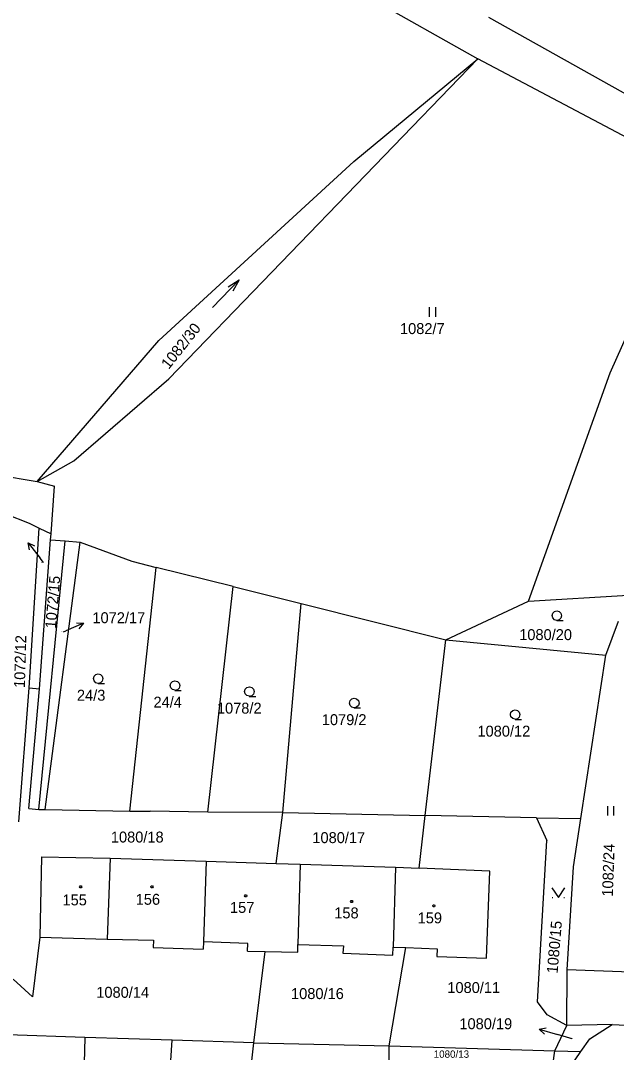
# Model space of a CAD drawing. Extents: x -850689 to -847910, y -1058374 to -1054747.
# Drawn here: x -849516.8 to -849424.1, y -1056255.5 to -1056094.9 of the extents above; entities that cross this region are included whole.
import ezdxf

# ---------------------------------------------------------------- set-up
doc = ezdxf.new("R2010")
doc.units = 0
for name, color, linetype in [('KN_HRANICE', 7, 'Continuous'), ('KN_KULTURY', 7, 'Continuous'), ('KN_PARCELY', 7, 'Continuous'), ('KN_STAVEBNI', 7, 'Continuous')]:
    doc.layers.add(name, color=color, linetype=linetype)

# ---------------------------------------------------------------- blocks, each defined once
blk = doc.blocks.new('304')
blk.add_lwpolyline([(0, 0), (-0.38, 0.1), (-0.65, 0.37), (-0.75, 0.74), (-0.65, 1.11), (-0.38, 1.38), (-0.01, 1.48), (0.36, 1.38), (0.63, 1.11), (0.73, 0.73), (0.63, 0.35), (0.36, 0.08), (-0.02, -0.02), (0.98, -0.02)])
blk = doc.blocks.new('306')
for p, q in [((-0.5, 1.5), (-0.5, 0)), ((0.5, 0), (0.5, 1.5))]:
    blk.add_line(p, q)
blk = doc.blocks.new('314')
for p, q in [((-0.95, 0), (-0.85, 0)), ((0.85, 0), (0.95, 0))]:
    blk.add_line(p, q)
blk.add_lwpolyline([(-1, 1.5), (0, 0), (1, 1.5)])
blk = doc.blocks.new('802')
blk.add_line((-3, 0), (3, 0))
blk.add_lwpolyline([(1, 0.5), (3, 0), (1, -0.5)])
blk = doc.blocks.new('10292')
blk.add_line((0, 3), (0, 0))
blk.add_lwpolyline([(-0.5, 2), (0, 3), (0.5, 2)])
blk = doc.blocks.new('402')
blk.add_lwpolyline([(0.09, 0.15), (0.18, 0), (0.09, -0.15), (-0.09, -0.15), (-0.18, 0), (-0.09, 0.15), (0.09, 0.15)])

msp = doc.modelspace()

# ---------------------------------------------------------------- linework, layer by layer
at = {"layer": 'KN_HRANICE'}
for p, q in [((-849544.37, -1056045.31), (-849445.63, -1056100.85)), ((-849443.99, -1056094.41), (-849418.2, -1056108.82)), ((-849493.74, -1056150.69), (-849445.63, -1056100.85)), ((-849464.96, -1056116.83), (-849445.63, -1056100.85)), ((-849411.33, -1056119.03), (-849445.63, -1056100.85)), ((-849495.31, -1056144.7), (-849464.96, -1056116.83)), ((-849425.04, -1056149.71), (-849411.33, -1056119.03)), ((-849514.22, -1056166.62), (-849495.31, -1056144.7)), ((-849508.53, -1056163.41), (-849493.74, -1056150.69)), ((-849437.73, -1056185.24), (-849425.04, -1056149.71)), ((-849514.22, -1056166.62), (-849508.53, -1056163.41)), ((-849524.53, -1056164.91), (-849514.22, -1056166.62)), ((-849514.22, -1056166.62), (-849511.52, -1056167.35)), ((-849512.08, -1056174.78), (-849511.52, -1056167.35)), ((-849519.17, -1056171.69), (-849515.51, -1056173.13)), ((-849515.51, -1056173.13), (-849513.93, -1056173.89)), ((-849515.49, -1056198.73), (-849513.93, -1056173.89)), ((-849513.93, -1056173.89), (-849512.08, -1056174.78)), ((-849512.15, -1056175.71), (-849512.08, -1056174.78)), ((-849513.99, -1056217.66), (-849509.86, -1056175.89)), ((-849513.9, -1056198.93), (-849512.15, -1056175.71)), ((-849512.99, -1056217.67), (-849507.57, -1056176.06)), ((-849512.15, -1056175.71), (-849509.86, -1056175.89)), ((-849509.86, -1056175.89), (-849507.57, -1056176.06)), ((-849507.57, -1056176.06), (-849499.52, -1056179.04)), ((-849499.52, -1056179.04), (-849495.72, -1056180)), ((-849499.82, -1056217.95), (-849495.72, -1056180)), ((-849483.74, -1056183), (-849495.72, -1056180)), ((-849487.67, -1056218.08), (-849483.74, -1056183)), ((-849483.74, -1056183), (-849473.17, -1056185.65)), ((-849437.73, -1056185.24), (-849422.22, -1056184.31)), ((-849476.02, -1056218.16), (-849473.17, -1056185.65)), ((-849473.17, -1056185.65), (-849450.63, -1056191.3)), ((-849450.63, -1056191.3), (-849437.73, -1056185.24)), ((-849425.74, -1056193.65), (-849423.72, -1056188.39)), ((-849453.82, -1056218.63), (-849450.63, -1056191.3)), ((-849450.63, -1056191.3), (-849425.74, -1056193.65)), ((-849429.59, -1056219.1), (-849425.74, -1056193.65)), ((-849517.12, -1056219.58), (-849515.49, -1056198.73)), ((-849515.53, -1056217.54), (-849513.9, -1056198.93)), ((-849515.49, -1056198.73), (-849513.9, -1056198.93)), ((-849515.53, -1056217.54), (-849513.99, -1056217.66)), ((-849513.99, -1056217.66), (-849512.99, -1056217.67)), ((-849512.99, -1056217.67), (-849499.82, -1056217.95)), ((-849499.82, -1056217.95), (-849496.64, -1056217.95)), ((-849487.67, -1056218.08), (-849496.64, -1056217.95)), ((-849476.02, -1056218.16), (-849487.67, -1056218.08)), ((-849477.02, -1056226.08), (-849476.02, -1056218.16)), ((-849476.02, -1056218.16), (-849453.82, -1056218.63)), ((-849454.77, -1056226.8), (-849453.82, -1056218.63)), ((-849436.49, -1056218.97), (-849453.82, -1056218.63)), ((-849436.49, -1056218.97), (-849429.59, -1056219.1)), ((-849436.49, -1056218.97), (-849434.92, -1056222.51)), ((-849430.73, -1056226.62), (-849429.59, -1056219.1)), ((-849436.33, -1056247.63), (-849434.92, -1056222.51)), ((-849513.55, -1056225.07), (-849513.82, -1056237.54)), ((-849513.55, -1056225.07), (-849502.89, -1056225.24)), ((-849502.89, -1056225.24), (-849503.37, -1056237.88)), ((-849502.89, -1056225.24), (-849487.95, -1056225.73)), ((-849487.95, -1056225.73), (-849488.36, -1056238.28)), ((-849487.95, -1056225.73), (-849477.02, -1056226.08)), ((-849477.02, -1056226.08), (-849473.29, -1056226.2)), ((-849473.29, -1056226.2), (-849473.65, -1056238.68)), ((-849473.29, -1056226.2), (-849458.46, -1056226.68)), ((-849458.46, -1056226.68), (-849458.8, -1056239.11)), ((-849458.46, -1056226.68), (-849454.77, -1056226.8)), ((-849443.79, -1056227.26), (-849454.77, -1056226.8)), ((-849444.27, -1056240.81), (-849443.79, -1056227.26)), ((-849431.74, -1056242.65), (-849430.73, -1056226.62)), ((-849513.82, -1056237.54), (-849514.98, -1056246.81)), ((-849513.82, -1056237.54), (-849503.37, -1056237.88)), ((-849503.37, -1056237.88), (-849496.11, -1056238)), ((-849496.11, -1056238), (-849496.18, -1056239.18)), ((-849496.18, -1056239.18), (-849488.39, -1056239.42)), ((-849488.36, -1056238.28), (-849488.39, -1056239.42)), ((-849481.46, -1056238.55), (-849488.36, -1056238.28)), ((-849481.51, -1056239.72), (-849481.46, -1056238.55)), ((-849473.68, -1056239.87), (-849473.65, -1056238.68)), ((-849473.65, -1056238.68), (-849466.55, -1056238.91)), ((-849466.55, -1056238.91), (-849466.66, -1056240.06)), ((-849459.44, -1056254.46), (-849456.85, -1056239.17)), ((-849458.87, -1056240.34), (-849458.8, -1056239.11)), ((-849458.8, -1056239.11), (-849456.85, -1056239.17)), ((-849456.85, -1056239.17), (-849451.95, -1056239.35)), ((-849481.51, -1056239.72), (-849478.74, -1056239.77)), ((-849480.53, -1056253.97), (-849478.74, -1056239.77)), ((-849478.74, -1056239.77), (-849473.68, -1056239.87)), ((-849466.66, -1056240.06), (-849458.87, -1056240.34)), ((-849451.95, -1056239.35), (-849452.03, -1056240.54)), ((-849452.03, -1056240.54), (-849444.27, -1056240.81)), ((-849431.76, -1056251.31), (-849431.74, -1056242.65)), ((-849421.86, -1056243), (-849431.74, -1056242.65)), ((-849514.98, -1056246.81), (-849517.97, -1056244.08)), ((-849434.87, -1056249.61), (-849436.33, -1056247.63)), ((-849431.76, -1056251.31), (-849434.87, -1056249.61)), ((-849433.67, -1056255.23), (-849431.76, -1056251.31)), ((-849424.74, -1056251.13), (-849431.76, -1056251.31)), ((-849428.22, -1056253.36), (-849424.74, -1056251.13)), ((-849424.74, -1056251.13), (-849362.03, -1056254.15)), ((-849506.8, -1056253.15), (-849518.79, -1056252.77)), ((-849506.8, -1056253.15), (-849508.04, -1056289.59)), ((-849493.22, -1056253.57), (-849506.8, -1056253.15)), ((-849494.45, -1056270.95), (-849493.22, -1056253.57)), ((-849480.53, -1056253.97), (-849493.22, -1056253.57)), ((-849429.59, -1056255.35), (-849428.22, -1056253.36)), ((-849482.35, -1056270.93), (-849480.53, -1056253.97)), ((-849480.53, -1056253.97), (-849459.44, -1056254.46)), ((-849459.46, -1056256.93), (-849459.44, -1056254.46)), ((-849459.44, -1056254.46), (-849433.67, -1056255.23)), ((-849433.96, -1056257.48), (-849433.67, -1056255.23)), ((-849433.67, -1056255.23), (-849429.59, -1056255.35)), ((-849431.37, -1056257.95), (-849429.59, -1056255.35))]:
    msp.add_line(p, q, dxfattribs=at)
at = {"layer": 'KN_PARCELY'}
for p, q in [((-849513.26, -1056179.26), (-849513.8, -1056178.56)), ((-849510.16, -1056190.04), (-849509.78, -1056189.88)), ((-849430.97, -1056253.37), (-849433.22, -1056252.71))]:
    msp.add_line(p, q, dxfattribs=at)
at = {"layer": 'KN_STAVEBNI'}
for p, q in [((-849513.55, -1056225.07), (-849513.82, -1056237.54)), ((-849513.55, -1056225.07), (-849502.89, -1056225.24)), ((-849502.89, -1056225.24), (-849503.37, -1056237.88)), ((-849502.89, -1056225.24), (-849503.37, -1056237.88)), ((-849502.89, -1056225.24), (-849487.95, -1056225.73)), ((-849487.95, -1056225.73), (-849477.02, -1056226.08)), ((-849477.02, -1056226.08), (-849473.29, -1056226.2)), ((-849473.29, -1056226.2), (-849473.65, -1056238.68)), ((-849473.29, -1056226.2), (-849473.65, -1056238.68)), ((-849473.29, -1056226.2), (-849458.46, -1056226.68)), ((-849458.46, -1056226.68), (-849454.77, -1056226.8)), ((-849443.79, -1056227.26), (-849454.77, -1056226.8)), ((-849444.27, -1056240.81), (-849443.79, -1056227.26)), ((-849513.82, -1056237.54), (-849503.37, -1056237.88)), ((-849503.37, -1056237.88), (-849496.11, -1056238)), ((-849496.11, -1056238), (-849496.18, -1056239.18)), ((-849496.18, -1056239.18), (-849488.39, -1056239.42)), ((-849488.36, -1056238.28), (-849488.39, -1056239.42)), ((-849481.46, -1056238.55), (-849488.36, -1056238.28)), ((-849481.51, -1056239.72), (-849481.46, -1056238.55)), ((-849473.68, -1056239.87), (-849473.65, -1056238.68)), ((-849473.65, -1056238.68), (-849466.55, -1056238.91)), ((-849466.55, -1056238.91), (-849466.66, -1056240.06)), ((-849458.87, -1056240.34), (-849458.8, -1056239.11)), ((-849458.8, -1056239.11), (-849456.85, -1056239.17)), ((-849456.85, -1056239.17), (-849451.95, -1056239.35)), ((-849481.51, -1056239.72), (-849478.74, -1056239.77)), ((-849478.74, -1056239.77), (-849473.68, -1056239.87)), ((-849466.66, -1056240.06), (-849458.87, -1056240.34)), ((-849451.95, -1056239.35), (-849452.03, -1056240.54)), ((-849452.03, -1056240.54), (-849444.27, -1056240.81))]:
    msp.add_line(p, q, dxfattribs=at)

# ---------------------------------------------------------------- block references
at = {"layer": 'KN_KULTURY', "rotation": 46.180398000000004}
msp.add_blockref('802', (-849484.85, -1056137.4), dxfattribs=at)
at = {"layer": 'KN_KULTURY'}
for name, p in [('306', (-849452.7, -1056141)), ('304', (-849433.34, -1056188.25)), ('304', (-849504.73, -1056198.05)), ('304', (-849492.78, -1056199.13)), ('304', (-849481.2, -1056200.06)), ('304', (-849464.87, -1056201.85)), ('304', (-849439.83, -1056203.64)), ('306', (-849424.97, -1056218.64)), ('402', (-849507.48, -1056229.7)), ('402', (-849496.39, -1056229.7)), ('402', (-849481.76, -1056231.12)), ('314', (-849433.1, -1056231.38)), ('402', (-849465.27, -1056231.98)), ('402', (-849452.49, -1056232.69))]:
    msp.add_blockref(name, p, dxfattribs=at)
at = {"layer": 'KN_PARCELY'}
for p, rotation in [((-849513.8, -1056178.56), 37.987102), ((-849509.78, -1056189.88), -66.64560900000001), ((-849433.22, -1056252.71), 73.682372)]:
    msp.add_blockref('10292', p, dxfattribs=dict(at, rotation=rotation))

# ---------------------------------------------------------------- texts
for s, rotation, p in [('1082/30', 51.566, (-849493.76, -1056149.28)), ('1072/15', 85.313, (-849511.31, -1056189.57)), ('1072/12', 88.407, (-849516.15, -1056198.78)), ('1082/24', 88.006, (-849424.62, -1056231.27)), ('1080/15', 85.142, (-849433.23, -1056243.26))]:
    msp.add_text(s, height=1.7, rotation=rotation, dxfattribs=at).set_placement(p)
for s, height, p in [('1082/7', 1.7, (-849457.76, -1056143.7)), ('1072/35', 0.1, (-849513.61, -1056179.26)), ('1072/17', 1.7, (-849505.64, -1056188.69)), ('1072/17', 0.1, (-849510.51, -1056190.04)), ('1080/20', 1.7, (-849439.2, -1056191.32)), ('24/3', 1.7, (-849508.05, -1056200.75)), ('24/4', 1.7, (-849496.14, -1056201.83)), ('1078/2', 1.7, (-849486.26, -1056202.76)), ('1079/2', 1.7, (-849469.93, -1056204.55)), ('1080/12', 1.7, (-849445.7, -1056206.34)), ('1080/18', 1.7, (-849502.77, -1056222.82)), ('1080/17', 1.7, (-849471.4, -1056222.91)), ('155', 1.7, (-849510.3, -1056232.6)), ('156', 1.7, (-849498.9, -1056232.51)), ('157', 1.7, (-849484.22, -1056233.77)), ('158', 1.7, (-849467.99, -1056234.63)), ('159', 1.7, (-849455.01, -1056235.4)), ('1080/14', 1.7, (-849505.04, -1056246.98)), ('1080/16', 1.7, (-849474.72, -1056247.18)), ('1080/11', 1.7, (-849450.39, -1056246.24)), ('1080/19', 1.7, (-849448.51, -1056251.87)), ('1080/19', 0.1, (-849431.31, -1056253.37)), ('1080/13', 1.14, (-849452.51, -1056256.32))]:
    msp.add_text(s, height=height, dxfattribs=at).set_placement(p)

doc.saveas('drawing.dxf')
